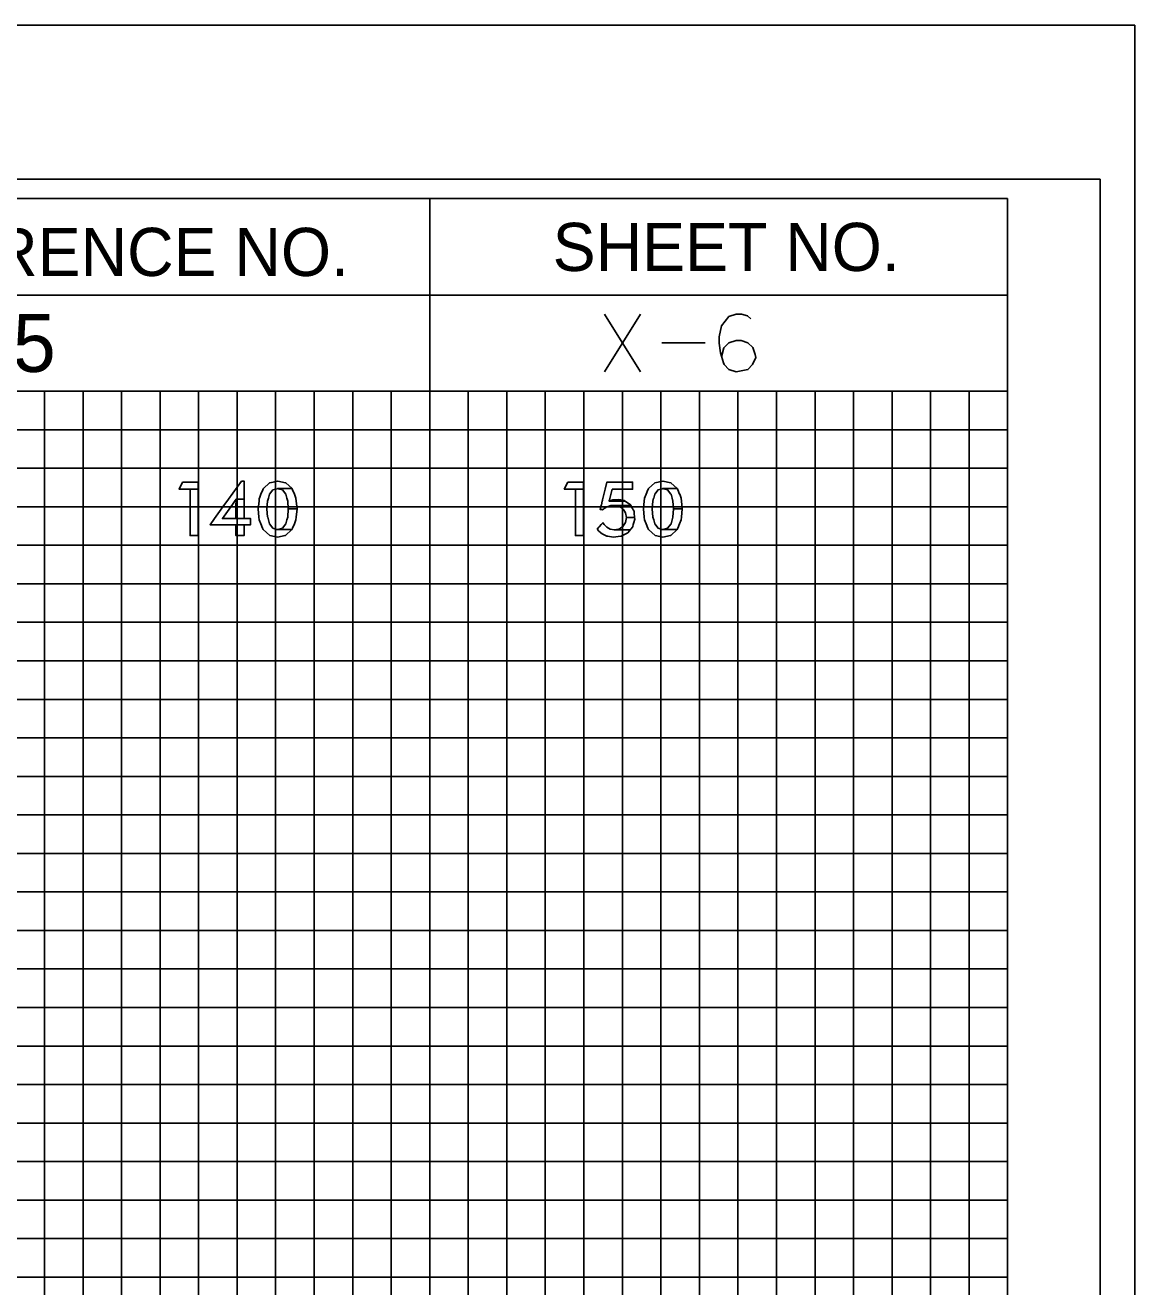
# Model space of a CAD drawing. Extents: x -13 to 323, y -5 to 1431.
# Drawn here: x 294.5 to 323.3, y 1061.75 to 1094.5 of the extents above; entities that cross this region are included whole.
import ezdxf

# ---------------------------------------------------------------- set-up
doc = ezdxf.new("R2010")
doc.units = 0
for name, color, linetype in [('Prop XS Offset Labels', 7, 'Continuous'), ('Prop XS Project Number', 7, 'Continuous'), ('Prop XS Sheet Number', 7, 'Continuous'), ('Sheet Cross Section CELL', 7, 'Continuous'), ('Sheet Cross Section Grid Major CELL', 7, 'Continuous'), ('Sheet Cross Section Grid Middle CELL', 7, 'Continuous'), ('Sheet Cross Section Grid Minor 1 CELL', 7, 'Continuous'), ('Sheet Cross Section Grid Minor 2 CELL', 7, 'Continuous'), ('Sheet Cutting Line CELL', 7, 'Continuous'), ('Sheet DOT Grid CELL', 7, 'Continuous'), ('Sheet Plot Border Inside CELL', 7, 'Continuous'), ('Sheet Plot Border Outside CELL', 7, 'Continuous')]:
    doc.layers.add(name, color=color, linetype=linetype)

msp = doc.modelspace()

# ---------------------------------------------------------------- linework, layer by layer
at = {"layer": 'Prop XS Offset Labels'}
for points in [[(298.581, 1082.641), (298.492, 1082.459), (298.99, 1082.459), (298.99, 1082.641)], [(298.781, 1082.459), (298.781, 1081.25), (298.99, 1081.25), (298.99, 1082.459)], [(299.411, 1081.693), (299.297, 1081.534), (300.35, 1081.534), (300.35, 1081.693), (299.618, 1081.693), (299.878, 1082.059), (299.935, 1082.139), (299.977, 1082.199), (300.179, 1082.199), (300.179, 1082.668), (300.114, 1082.668), (299.775, 1082.199), (299.733, 1082.139), (299.675, 1082.059)], [(300.851, 1081.255), (301.051, 1081.214), (301.245, 1081.255), (301.256, 1081.257), (301.422, 1081.409), (301.048, 1081.409), (301.038, 1081.411), (301.033, 1081.413), (300.928, 1081.442), (300.841, 1081.555), (300.841, 1081.556), (300.841, 1081.556), (300.813, 1081.657), (300.813, 1081.659), (300.793, 1081.732), (300.792, 1081.736), (300.774, 1081.939), (300.774, 1081.941), (300.774, 1081.943), (300.792, 1082.145), (300.812, 1082.222), (300.813, 1082.224), (300.839, 1082.322), (300.84, 1082.325), (300.928, 1082.44), (301.041, 1082.469), (301.045, 1082.47), (301.055, 1082.473), (301.425, 1082.473), (301.262, 1082.622), (301.254, 1082.624), (301.053, 1082.668), (301.053, 1082.668), (300.845, 1082.624), (300.843, 1082.622), (300.681, 1082.473), (300.678, 1082.47), (300.678, 1082.469), (300.665, 1082.44), (300.618, 1082.325), (300.617, 1082.322), (300.577, 1082.224), (300.576, 1082.222), (300.568, 1082.145), (300.547, 1081.943), (300.547, 1081.941), (300.547, 1081.939), (300.567, 1081.736), (300.567, 1081.732), (300.575, 1081.659), (300.575, 1081.657), (300.616, 1081.556), (300.617, 1081.555), (300.663, 1081.442), (300.675, 1081.413), (300.676, 1081.411), (300.679, 1081.409), (300.848, 1081.257)], [(301.312, 1082.145), (301.328, 1081.943), (301.555, 1081.943), (301.536, 1082.145), (301.528, 1082.222), (301.528, 1082.224), (301.527, 1082.224), (301.488, 1082.322), (301.488, 1082.322), (301.487, 1082.325), (301.441, 1082.44), (301.44, 1082.44), (301.429, 1082.469), (301.428, 1082.47), (301.425, 1082.473), (301.055, 1082.473), (301.065, 1082.47), (301.068, 1082.469), (301.175, 1082.44), (301.262, 1082.325), (301.265, 1082.322), (301.291, 1082.224), (301.291, 1082.222)], [(308.581, 1082.641), (308.492, 1082.459), (308.99, 1082.459), (308.99, 1082.641)], [(308.781, 1082.459), (308.781, 1081.25), (308.99, 1081.25), (308.99, 1082.459)], [(309.427, 1081.94), (309.424, 1081.928), (309.495, 1081.928), (309.508, 1081.94), (309.524, 1081.954), (309.595, 1081.997), (309.627, 1082.007), (309.697, 1082.029), (309.811, 1082.035), (310.219, 1082.035), (310.211, 1082.05), (310.076, 1082.145), (309.655, 1082.145), (309.658, 1082.158), (309.658, 1082.158), (309.663, 1082.178), (309.738, 1082.456), (310.263, 1082.456), (310.263, 1082.641), (309.6, 1082.641), (309.554, 1082.456), (309.486, 1082.178), (309.481, 1082.158), (309.478, 1082.145), (309.454, 1082.05), (309.451, 1082.035), (309.449, 1082.029), (309.444, 1082.007), (309.441, 1081.997), (309.431, 1081.954)], [(310.851, 1081.255), (311.051, 1081.214), (311.245, 1081.255), (311.256, 1081.257), (311.422, 1081.409), (311.048, 1081.409), (311.038, 1081.411), (311.033, 1081.413), (310.928, 1081.442), (310.841, 1081.555), (310.841, 1081.556), (310.841, 1081.556), (310.813, 1081.657), (310.813, 1081.659), (310.793, 1081.732), (310.792, 1081.736), (310.774, 1081.939), (310.774, 1081.941), (310.774, 1081.943), (310.792, 1082.145), (310.812, 1082.222), (310.813, 1082.224), (310.839, 1082.322), (310.84, 1082.325), (310.928, 1082.44), (311.041, 1082.469), (311.045, 1082.47), (311.055, 1082.473), (311.425, 1082.473), (311.262, 1082.622), (311.254, 1082.624), (311.053, 1082.668), (311.053, 1082.668), (310.845, 1082.624), (310.843, 1082.622), (310.681, 1082.473), (310.678, 1082.47), (310.678, 1082.469), (310.665, 1082.44), (310.618, 1082.325), (310.617, 1082.322), (310.577, 1082.224), (310.576, 1082.222), (310.568, 1082.145), (310.547, 1081.943), (310.547, 1081.941), (310.547, 1081.939), (310.567, 1081.736), (310.567, 1081.732), (310.575, 1081.659), (310.575, 1081.657), (310.616, 1081.556), (310.617, 1081.555), (310.663, 1081.442), (310.675, 1081.413), (310.676, 1081.411), (310.679, 1081.409), (310.848, 1081.257)], [(311.312, 1082.145), (311.328, 1081.943), (311.555, 1081.943), (311.536, 1082.145), (311.528, 1082.222), (311.528, 1082.224), (311.527, 1082.224), (311.488, 1082.322), (311.488, 1082.322), (311.487, 1082.325), (311.441, 1082.44), (311.44, 1082.44), (311.429, 1082.469), (311.428, 1082.47), (311.425, 1082.473), (311.055, 1082.473), (311.065, 1082.47), (311.068, 1082.469), (311.175, 1082.44), (311.262, 1082.325), (311.265, 1082.322), (311.291, 1082.224), (311.291, 1082.222)], [(299.97, 1082.059), (299.97, 1081.693), (300.179, 1081.693), (300.179, 1082.059), (300.179, 1082.139), (300.179, 1082.199), (299.977, 1082.199), (299.973, 1082.139)], [(309.692, 1082.158), (309.655, 1082.145), (310.076, 1082.145), (310.058, 1082.158), (309.961, 1082.178), (309.75, 1082.178)], [(309.888, 1082.192), (309.75, 1082.178), (309.96, 1082.178), (309.888, 1082.192)], [(301.058, 1081.411), (301.048, 1081.409), (301.422, 1081.409), (301.425, 1081.411), (301.426, 1081.413), (301.438, 1081.442), (301.485, 1081.555), (301.485, 1081.556), (301.527, 1081.657), (301.528, 1081.659), (301.535, 1081.732), (301.535, 1081.736), (301.555, 1081.939), (301.556, 1081.941), (301.555, 1081.943), (301.328, 1081.943), (301.328, 1081.941), (301.328, 1081.939), (301.312, 1081.736), (301.312, 1081.732), (301.292, 1081.659), (301.291, 1081.657), (301.264, 1081.556), (301.263, 1081.555), (301.175, 1081.442), (301.063, 1081.413)], [(309.424, 1081.928), (309.482, 1081.916), (309.495, 1081.928)], [(310.083, 1081.841), (310.105, 1081.721), (310.318, 1081.721), (310.307, 1081.841), (310.307, 1081.841), (310.303, 1081.881), (310.284, 1081.916), (310.278, 1081.928), (310.271, 1081.94), (310.263, 1081.954), (310.24, 1081.997), (310.235, 1082.007), (310.223, 1082.029), (310.219, 1082.035), (309.811, 1082.035), (309.838, 1082.029), (309.928, 1082.007), (309.942, 1081.997), (310.003, 1081.954), (310.024, 1081.94), (310.031, 1081.928), (310.038, 1081.916), (310.059, 1081.881)], [(311.058, 1081.411), (311.048, 1081.409), (311.422, 1081.409), (311.425, 1081.411), (311.426, 1081.413), (311.438, 1081.442), (311.485, 1081.555), (311.485, 1081.556), (311.527, 1081.657), (311.528, 1081.659), (311.535, 1081.732), (311.535, 1081.736), (311.555, 1081.939), (311.556, 1081.941), (311.555, 1081.943), (311.328, 1081.943), (311.328, 1081.941), (311.328, 1081.939), (311.312, 1081.736), (311.312, 1081.732), (311.292, 1081.659), (311.291, 1081.657), (311.264, 1081.556), (311.263, 1081.555), (311.175, 1081.442), (311.063, 1081.413)], [(299.97, 1081.534), (299.97, 1081.25), (300.179, 1081.25), (300.179, 1081.534)], [(309.626, 1081.233), (309.762, 1081.214), (309.959, 1081.233), (309.968, 1081.237), (310.091, 1081.297), (310.091, 1081.297), (310.141, 1081.321), (310.185, 1081.375), (310.204, 1081.399), (309.793, 1081.399), (309.683, 1081.418), (309.682, 1081.419), (309.679, 1081.42), (309.596, 1081.466), (309.586, 1081.477), (309.58, 1081.483), (309.58, 1081.483), (309.529, 1081.535), (309.497, 1081.585), (309.497, 1081.585), (309.451, 1081.535), (309.404, 1081.483), (309.399, 1081.477), (309.39, 1081.466), (309.348, 1081.42), (309.347, 1081.419), (309.348, 1081.418), (309.363, 1081.399), (309.382, 1081.375), (309.445, 1081.321), (309.474, 1081.297), (309.598, 1081.237)], [(309.9, 1081.418), (309.793, 1081.399), (310.204, 1081.399), (310.22, 1081.418), (310.221, 1081.419), (310.222, 1081.42), (310.222, 1081.42), (310.259, 1081.466), (310.268, 1081.477), (310.27, 1081.483), (310.284, 1081.535), (310.299, 1081.59), (310.322, 1081.674), (310.318, 1081.721), (310.105, 1081.721), (310.097, 1081.674), (310.082, 1081.59), (310.047, 1081.535), (310.014, 1081.483), (310.004, 1081.477), (309.987, 1081.466), (309.913, 1081.42), (309.905, 1081.419)]]:
    msp.add_lwpolyline(points, close=True, dxfattribs=at)
at = {"layer": 'Prop XS Sheet Number'}
for p, q in [((309.539, 1087), (310.472, 1085.5)), ((310.472, 1087), (309.539, 1085.5)), ((311.028, 1086.256), (312.15, 1086.256))]:
    msp.add_line(p, q, dxfattribs=at)
msp.add_lwpolyline([(313.331, 1086.882), (313.248, 1086.953), (313.094, 1087), (312.953, 1087), (312.764, 1086.941), (312.575, 1086.693), (312.516, 1086.409), (312.516, 1086.244), (312.551, 1085.996), (312.622, 1085.736), (312.646, 1085.689), (312.764, 1085.559), (312.953, 1085.5), (313.26, 1085.559), (313.378, 1085.689), (313.461, 1085.878), (313.449, 1085.949), (313.39, 1086.138), (313.26, 1086.256), (313.083, 1086.315), (312.953, 1086.315), (312.764, 1086.256), (312.634, 1086.126), (312.575, 1085.89)], dxfattribs=at)
at = {"layer": 'Sheet Cross Section CELL'}
for p, q in [((305, 1090), (305, 1085)), ((305, 1085), (305, 1090)), ((320, 1087.49), (280, 1087.49)), ((280, 1085), (320, 1085))]:
    msp.add_line(p, q, dxfattribs=at)
for points in [[(320, 1090), (0, 1090), (0, 880), (320, 880)], [(320, 1090), (280, 1090), (280, 1085), (320, 1085)]]:
    msp.add_lwpolyline(points, close=True, dxfattribs=at)
at = {"layer": 'Sheet Cross Section Grid Major CELL'}
for p, q in [((310, 1085), (300, 1085)), ((300, 1085), (300, 880)), ((310, 880), (310, 1085))]:
    msp.add_line(p, q, dxfattribs=at)
msp.add_lwpolyline([(0, 1080), (320, 1080), (320, 1070), (0, 1070)], dxfattribs=at)
at = {"layer": 'Sheet Cross Section Grid Middle CELL'}
for points in [[(295, 880), (295, 1085), (305, 1085), (305, 880)], [(315, 880), (315, 1085)], [(0, 1065), (320, 1065), (320, 1075), (0, 1075)]]:
    msp.add_lwpolyline(points, dxfattribs=at)
at = {"layer": 'Sheet Cross Section Grid Minor 1 CELL'}
msp.add_line((0, 1084), (320, 1084), dxfattribs=at)
for points in [[(0, 1083), (270, 1083), (320, 1083), (320, 1082), (0, 1082)], [(0, 1081), (320, 1081), (320, 1079), (0, 1079)], [(0, 1078), (320, 1078), (320, 1077), (0, 1076.98)], [(0, 1076), (320, 1076), (320, 1074), (0, 1074)], [(0, 1073), (320, 1073), (320, 1072), (0, 1072)], [(0, 1071), (320, 1071), (320, 1069), (0, 1069)], [(0, 1068), (320, 1068), (320, 1067), (0, 1067)], [(0, 1066), (320, 1066), (320, 1064), (0, 1064)], [(0, 1063), (320, 1063), (320, 1062), (0, 1062)]]:
    msp.add_lwpolyline(points, dxfattribs=at)
at = {"layer": 'Sheet Cross Section Grid Minor 2 CELL'}
for points in [[(295, 880), (296, 880), (296, 1085), (297, 1085), (297, 880)], [(297, 880), (298, 880), (298, 1085), (299, 1085), (299, 880)], [(300, 880), (301, 880), (301, 1085), (302, 1085), (302, 880)], [(302, 880), (303, 880), (303, 1085), (304, 1085), (304, 880)], [(305, 880), (306, 880), (306, 1085), (307, 1085), (307, 880)], [(307, 880), (308, 880), (308, 1085), (309, 1085), (309, 880)], [(310, 880), (311, 880), (311, 1085), (312, 1085), (312, 880)], [(312, 880), (313, 880), (313, 1085), (314, 1085), (314, 880)], [(315, 880), (316, 880), (316, 1085), (317, 1085), (317, 880)], [(317, 880), (318, 880), (318, 1085), (319, 1085), (319, 880)]]:
    msp.add_lwpolyline(points, dxfattribs=at)
at = {"layer": 'Sheet Cutting Line CELL'}
msp.add_line((323.3, 1094.5), (-13.4, 1094.5), dxfattribs=at)
at = {"layer": 'Sheet DOT Grid CELL'}
for p, q in [((300, 880), (300, 1084.687)), ((310, 880), (310, 1084.687)), ((0, 1080), (320, 1080)), ((0, 1070), (320, 1070))]:
    msp.add_line(p, q, dxfattribs=at)
at = {"layer": 'Sheet Plot Border Inside CELL'}
msp.add_lwpolyline([(-10.8, 879.5), (322.4, 879.5), (322.4, 1090.5), (-10.8, 1090.5)], close=True, dxfattribs=at)
at = {"layer": 'Sheet Plot Border Outside CELL'}
msp.add_lwpolyline([(-13.4, 875.5), (323.3, 875.5), (323.3, 1094.5), (-13.4, 1094.5)], close=True, dxfattribs=at)

# ---------------------------------------------------------------- texts
at = {"layer": 'Prop XS Project Number'}
msp.add_text('HL-0025', height=1.5, dxfattribs=at).set_placement((287.598, 1085.5))
at = {"layer": 'Sheet Cross Section CELL'}
for s, height, p in [('SHEET NO.', 1.25, (308.19, 1088.12)), ('PROJ. REFERENCE NO.', 1.24998, (283.77, 1087.99))]:
    msp.add_text(s, height=height, dxfattribs=at).set_placement(p)

doc.saveas('drawing.dxf')
